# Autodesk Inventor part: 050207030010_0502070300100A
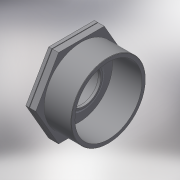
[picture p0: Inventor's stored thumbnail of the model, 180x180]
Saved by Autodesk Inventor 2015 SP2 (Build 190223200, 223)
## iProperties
Created: 2017-05
Part Number: 050207030010_0502070300100A
Material: Generic
Description: PLASSON REDUCING BUSHING 3"-1"
Document SubType Name: Modeling
Designer: KIM
Density: 1 g/cm^3
Appearance: Default
Author: KIM
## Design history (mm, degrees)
derived "050207.ipt"
feature "Solid1::050207.ipt"
tag "TaggingFeature1"
body "Solid1"
other parameters: "d1" = 87.884, "d5" = 32, "d8" = 0.48, "d12" = 0, "d15" = 48, "d19" = 0, "d30" = 9.6, "d31" = 4.8, "d33" = 30.291, "d34" = 79.0956, "d36" = 4.5, "d37" = 36.3492, "d38" = 31.68, "d39" = 27.2619, "d40" = 3.2, "d41" = 0, "H_" = 48, "R_" = 87.884, "l_2" = 32, "Rp_" = 30.291
